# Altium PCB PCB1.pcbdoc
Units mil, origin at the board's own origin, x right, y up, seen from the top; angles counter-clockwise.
Board outline 3432.54 x 1243.82 mil, 4 copper layers (Top Layer, GND, VCC, Bottom Layer); 58 components, 43 nets, 212 pads, 108 vias.
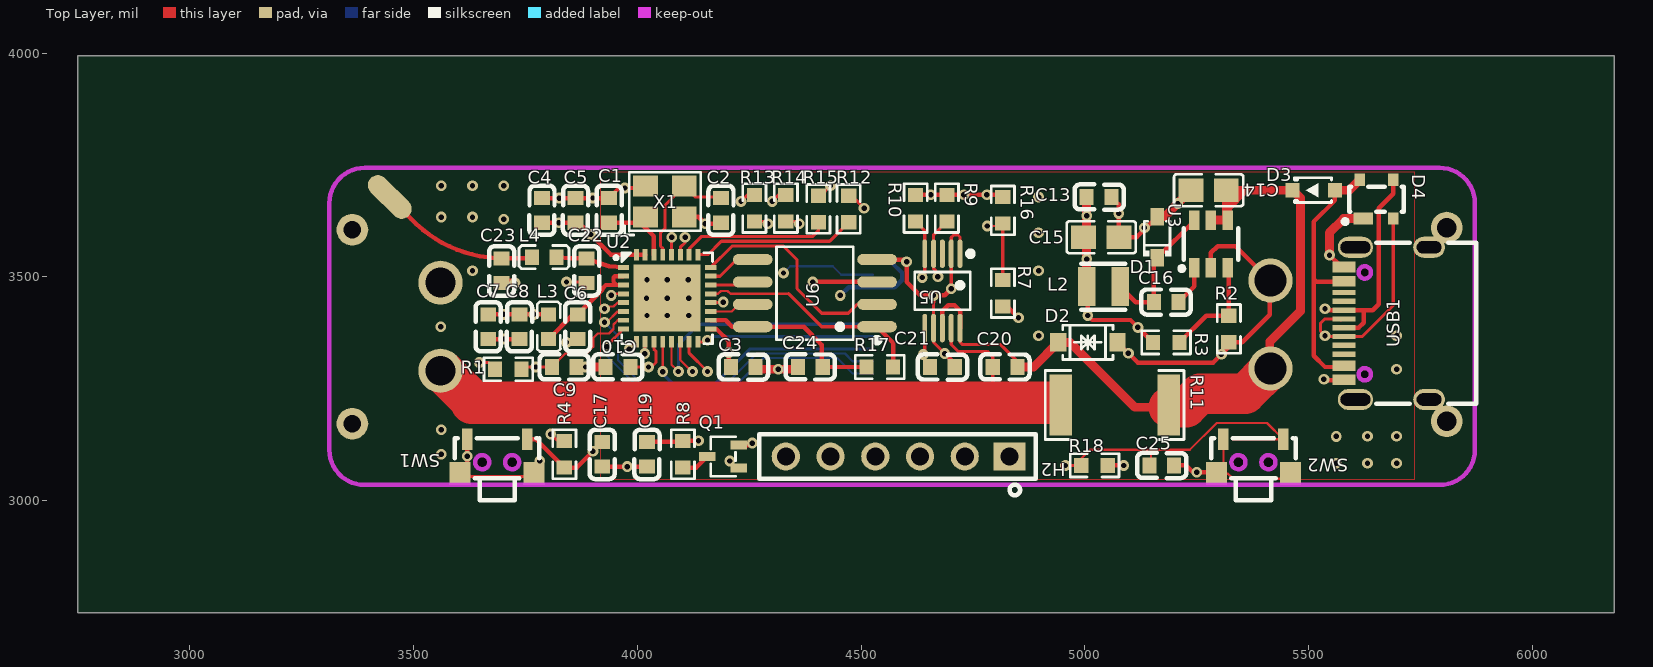
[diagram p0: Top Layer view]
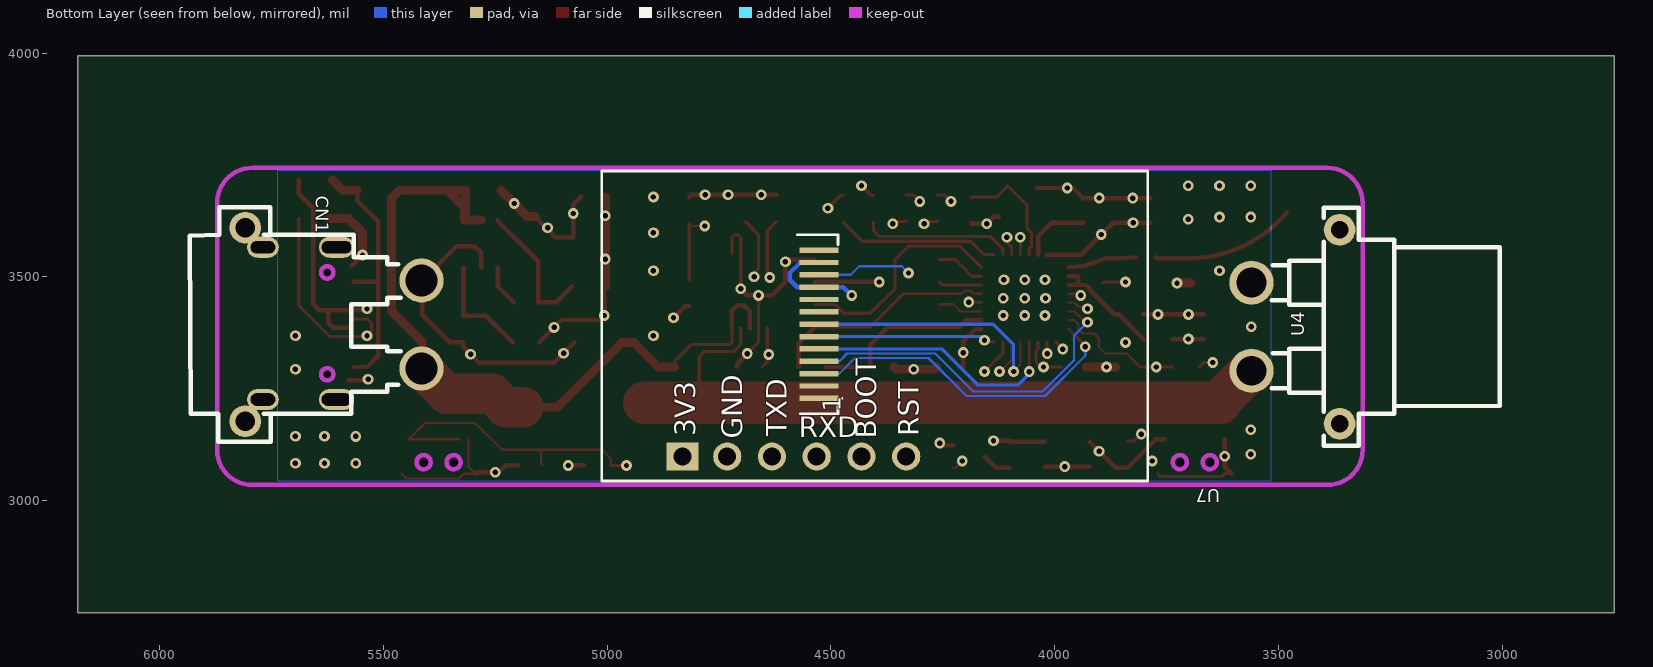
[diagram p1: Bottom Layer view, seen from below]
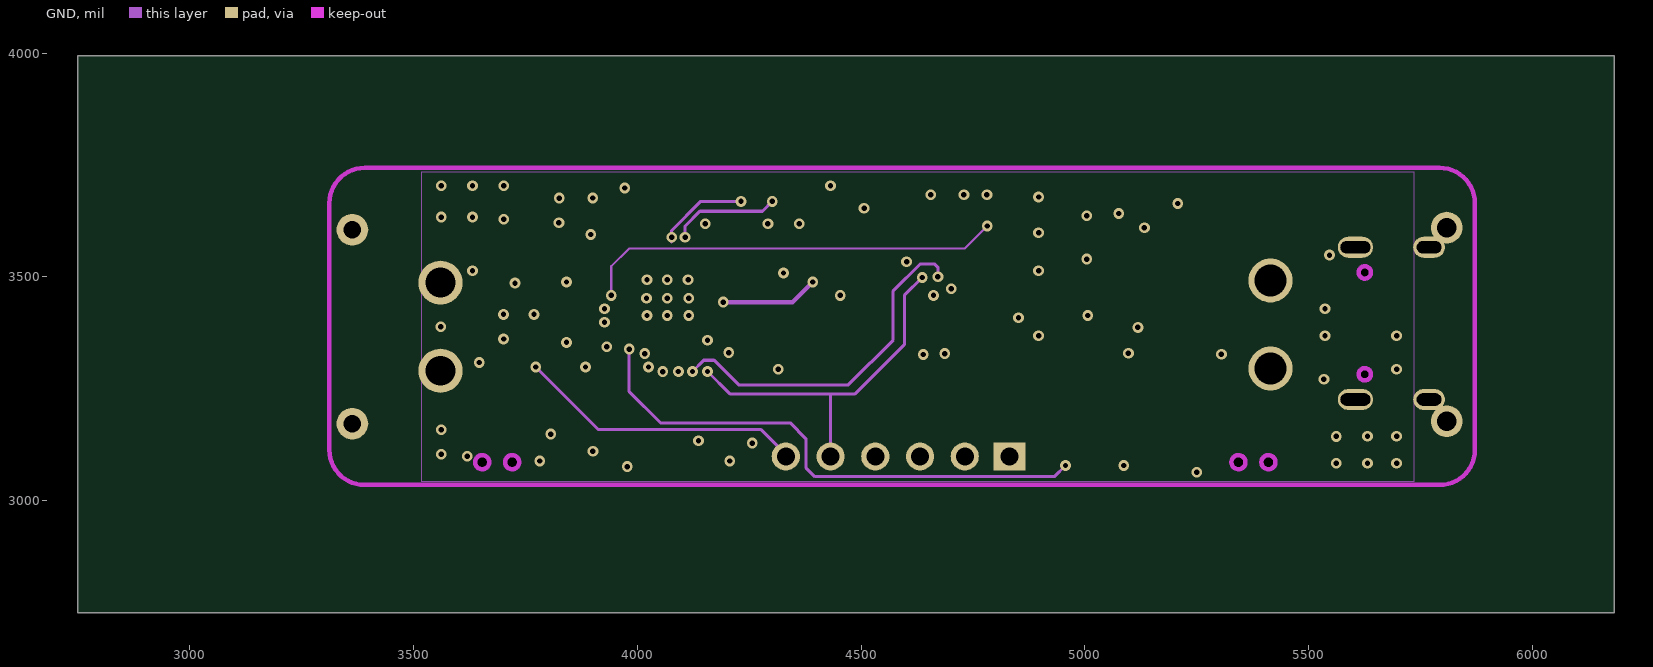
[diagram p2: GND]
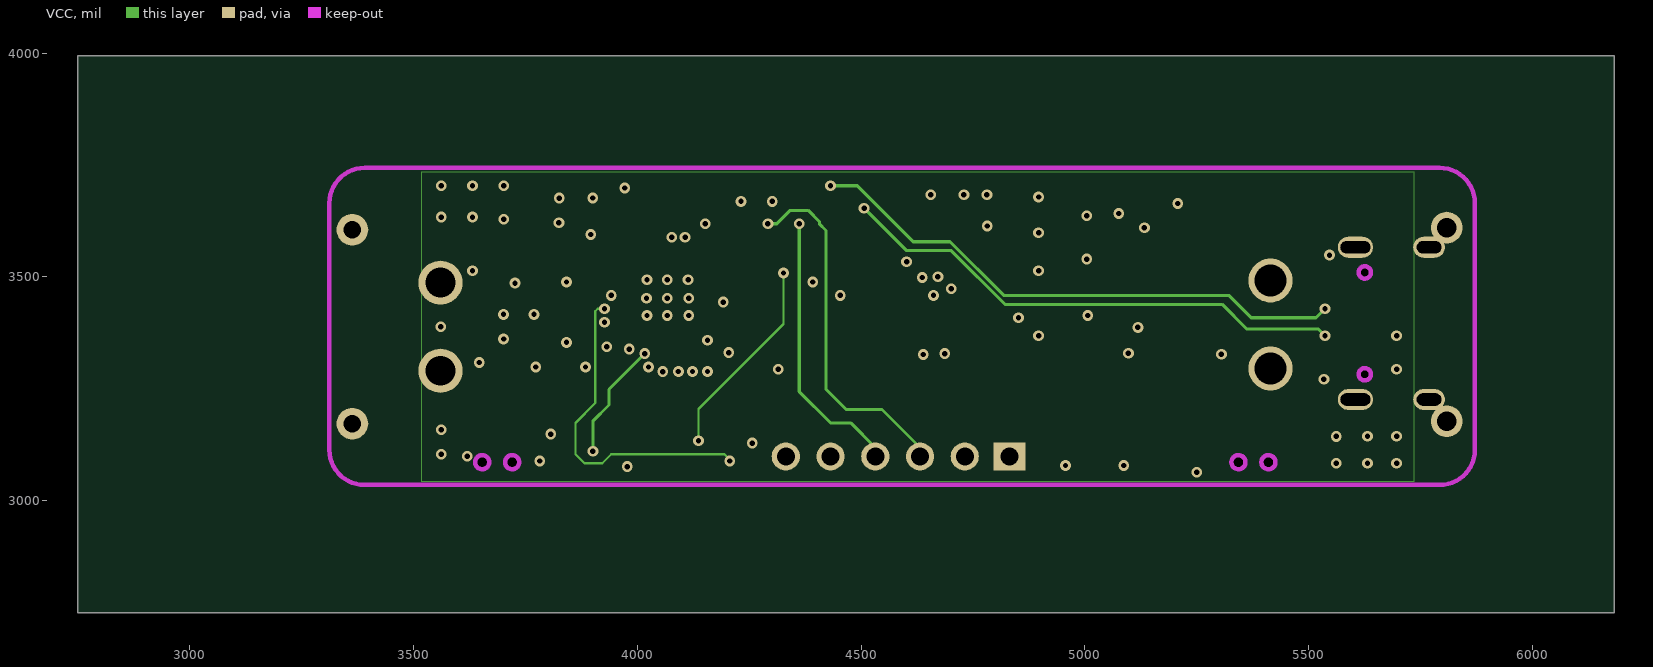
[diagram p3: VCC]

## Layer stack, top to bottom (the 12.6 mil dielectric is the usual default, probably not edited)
Top Layer: signal copper (thickness not stored)
Dielectric: dielectric 12.6, FR-4, Dk 4.8
GND: signal copper (thickness not stored)
Dielectric: dielectric 12.6, FR-4, Dk 4.8
VCC: signal copper (thickness not stored)
Dielectric: dielectric 12.6, FR-4, Dk 4.8
Bottom Layer: signal copper (thickness not stored)

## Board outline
6182.54,2750 2750,2750 2750,3993.82 6182.54,3993.82

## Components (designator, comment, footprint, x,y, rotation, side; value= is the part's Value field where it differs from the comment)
C1 "CC0603JRNPO9BN220" C0603 3936.69,3648.82 r270 top
C2 "CC0603JRNPO9BN220" C0603 4186.69,3648.82 r270 top
C3 "0603B104K500NT" C0603 4236.69,3298.82 r180 top
C4 "CL10A105KB8NNNC" C0603 3786.69,3648.82 r270 top
C5 "CL10A106KP8NNNC" C0603 3861.69,3648.82 r270 top
C6 "CL10A105KB8NNNC" C0603 3866.69,3388.82 r90 top
C7 "CL10A106KP8NNNC" C0603 3666.69,3388.82 r90 top
C8 "0603B104K500NT" C0603 3736.69,3388.82 r90 top
C9 "0603B104K500NT" C0603 3836.69,3298.82 r0 top
C10 "0603B104K500NT" C0603 3956.69,3298.82 r0 top
C13 "0603B104K500NT" C0603 5031.69,3678.82 r180 top
C14 "CL21A475KAQNNNE" C0805 5276.69,3693.82 r0 top
C15 "CL21A226MAQNNNE" C0805 5036.69,3588.82 r180 top
C16 "0603B104K500NT" C0603 5181.69,3443.82 r0 top
C17 "0603B104K500NT" C0603 3921.69,3103.82 r90 top
C19 "CL10A106KP8NNNC" C0603 4021.69,3103.82 r90 top
C20 "0603B104K500NT" C0603 4821.69,3298.82 r0 top
C21 "0603B104K500NT" C0603 4681.69,3298.82 r180 top
C22 "CAP_0603" C0603 3886.69,3513.82 r90 top
C23 "CAP_0603" C0603 3696.69,3513.82 r90 top
C24 "CL10A105KB8NNNC" C0603 4386.69,3298.82 r0 top
C25 "0603B104K500NT" C0603 5171.69,3078.82 r180 top
CN1 "XT30PW-M" CONN-TH_XT30PW-M 5611.69,3393.82 r270 bottom
D1 "1N5819WS_C191023" SOD-323_L1.8-W1.3-LS2.5-RD 5161.69,3588.82 r90 top
D2 "SMF26CA_C435495" SOD-123_L2.8-W1.8-LS3.7-BI 5006.69,3353.82 r0 top
D3 "S7116-300A" SOD-323_L1.7-W1.3-LS2.5-RD 5511.69,3693.82 r0 top
D4 "BST143A053U" SOT-143_L2.9-W1.3-P1.92-LS2.3-BR 5651.69,3673.82 r270 top
H2 "HDR-F_2.54_1x6P" HDR-TH_6P-P2.54-V-F 4581.69,3098.82 r180 top
L2 "FHD252012S-100MT" IND-SMD_L2.5-W2.0_FHD252012S-6R8MT 5041.69,3478.82 r180 top
L3 "VHF160808H2N0ST" L0603 3801.69,3388.82 r270 top
L4 "L_0603" L0603 3791.69,3543.82 r0 top
Q1 "DTC114EUA_C55054" SOT-323-3_L2.0-W1.3-P1.30-LS2.1-BR 4191.69,3098.82 r0 top
R1 "0603WAF1002T5E" R0603 3711.69,3293.82 r0 top
R2 "RT0603BRD071K02L" R0603 5321.69,3383.82 r90 top
R3 "RT0603BRD073K4L" R0603 5181.69,3353.82 r0 top
R4 "0603WAF1002T5E" R0603 3836.69,3103.82 r90 top
R7 "0603WAF1002T5E" R0603 4816.69,3463.82 r90 top
R8 "0603WAF100JT5E" R0603 4101.69,3103.82 r90 top
R9 "0603WAF4701T5E" R0603 4691.69,3653.82 r270 top
R10 "0603WAF4701T5E" R0603 4621.69,3653.82 r270 top
R11 "PA2512FKE7T0R01E" R2512 5066.69,3213.82 r180 top
R12 "0603WAF390JT5E" R0603 4472.2,3652.04 r270 top
R13 "0603WAF3300T5E" R0603 4261.69,3653.82 r90 top
R14 "0603WAF3300T5E" R0603 4331.69,3653.82 r90 top
R15 "0603WAF390JT5E" R0603 4404.51,3652.04 r270 top
R16 "SDNT1608X103F3450FTF" R0603 4816.69,3648.82 r90 top
R17 "0603WAF1002T5E" R0603 4541.69,3298.82 r180 top
R18 "0603WAF1002T5E" R0603 5021.69,3078.82 r0 top
SW1 "TS-1010-C-A" KEY-SMD_TX-1010-X-X 3686.69,3098.82 r180 top
SW2 "TS-1010-C-A" KEY-SMD_TX-1010-X-X 5376.69,3098.82 r180 top
U2 "ESP32-C3" QFN-32_L5.0-W5.0-P0.50-TL-EP3.7 4066.55,3452.51 r0 top
U3 "LM2841XBMKX/NOPB" SOT-23-6_L2.9-W1.6-P0.95-LS2.8-BR 5281.69,3573.82 r270 top
U4 "XT30PW-F" CONN-TH_XT30PW-F-1 3461.69,3388.82 r90 bottom
U5 "INA226AIDGSR" MSOP-10_L3.0-W3.0-P0.50-LS5.0-BL 4681.69,3468.82 r180 top
U6 "W25Q128JVSIQ" SOIC-8_L5.3-W5.3-P1.27-LS8.0-BL 4396.69,3463.82 r90 top
U7 "ST7789" ST7789 4526.69,3228.82 r0 bottom
USB1 "HC-TYPE-C-16P-01B" USB_TYPE-C-16P 5674.19,3391.32 r90 top
X1 "X322540MPB4SI" OSC-SMD_4P-L3.2-W2.5-BL 4061.69,3668.82 r0 top

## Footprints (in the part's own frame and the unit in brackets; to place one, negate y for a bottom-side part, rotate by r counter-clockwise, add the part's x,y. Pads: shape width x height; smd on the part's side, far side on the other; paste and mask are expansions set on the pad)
C0603 [mm]
  rect 0.8x0.9 smd: 1(-0.7,0) 2(0.7,0)
  silkscreen extent -1.41,-0.71 1.39,0.72
C0805 [mm]
  rect 1.41x1.35 smd: 1(-1,0) 2(1,0)
  silkscreen extent -1.96,-0.9 1.96,0.9
CONN-TH_XT30PW-F-1 [mm]
  round 2.5 hole 1.7 copper offset 0,0: 1(-2.5,2.5) 2(2.5,2.5)
  round 1.8 hole 1 copper offset 0,0: 3(5.5,-2.5) 4(-5.5,-2.5)
  silkscreen extent -6.75,-11.6 6.75,1.35
CONN-TH_XT30PW-M [mm]
  round 2.5 hole 1.8: 1(-2.5,5) 2(2.5,5)
  round 1.8 hole 1.1: 3(5.5,-5) 4(-5.5,-5)
  silkscreen extent -6.65,-8.15 6.65,3.81
HDR-TH_6P-P2.54-V-F [mm]
  rect 1.8x1.6 hole 1.02: 1(-6.35,0)
  round 1.6 hole 1.02: 2(-3.81,0) 3(-1.27,0) 4(1.27,0) 5(3.81,0) 6(6.35,0)
  silkscreen extent -7.85,-1.25 7.85,2.2
IND-SMD_L2.5-W2.0_FHD252012S-6R8MT [mm]
  rect 1x2.2 smd: 1(-0.951,0) 2(0.95,0)
  silkscreen extent -1.24,-1.3 1.26,1.32
KEY-SMD_TX-1010-X-X [mm]
  rect 0.6x1.2 smd: 1(-1.7,-0.975) 2(1.7,-0.975)
  rect 1.2x1.3 smd: 3(-2.1,0.975) 4(2.1,0.975)
  Multi-Layer board cut-out: -1.25,0.325 -1.21,0.151 -1.099,0.012 -0.939,-0.065 -0.761,-0.065 -0.6,0.012 -0.489,0.152 -0.45,0.325 -0.45,0.325 -0.489,0.499 -0.6,0.638 -0.761,0.715 -0.939,0.715 -1.099,0.638 -1.21,0.499 -1.25,0.325
  Multi-Layer board cut-out: 0.45,0.325 0.49,0.151 0.601,0.012 0.761,-0.065 0.939,-0.065 1.1,0.012 1.211,0.152 1.25,0.325 1.25,0.325 1.211,0.499 1.1,0.638 0.939,0.715 0.761,0.715 0.601,0.638 0.49,0.499 0.45,0.325
  silkscreen extent -2.4,-1.03 2.4,2.48
L0603 [mm]
  rect 0.8x0.864 smd: 1(-0.7,0) 2(0.7,0)
  silkscreen extent -1.42,-0.65 1.41,0.67
MSOP-10_L3.0-W3.0-P0.50-LS5.0-BL [mm]
  oval 0.28x1.62 smd: 1(-1,-2.11) 2(-0.5,-2.11) 3(0,-2.11) 4(0.5,-2.11) 5(1,-2.11) 6(1,2.11) 7(0.5,2.11) 8(0,2.11) 9(-0.5,2.11) 10(-1,2.11)
  silkscreen extent -1.74,-2.26 1.58,1.07
OSC-SMD_4P-L3.2-W2.5-BL [mm]
  rect 1.4x1.2 smd: 1(-1.1,-0.875) 2(1.1,-0.875) 3(1.1,0.875) 4(-1.1,0.875)
  silkscreen extent -2.29,-1.9 2.03,1.65
QFN-32_L5.0-W5.0-P0.50-TL-EP3.7 [mm]
  rect 0.65x0.28 smd: 1(-2.478,1.75) 2(-2.478,1.25) 3(-2.478,0.75) 4(-2.478,0.25) 5(-2.478,-0.25) 6(-2.478,-0.75) 7(-2.478,-1.25) 8(-2.478,-1.75) 17(2.478,-1.75) 18(2.478,-1.25) 19(2.478,-0.75) 20(2.478,-0.25) 21(2.478,0.25) 22(2.478,0.75) 23(2.478,1.25) 24(2.478,1.75)
  rect 0.28x0.65 smd: 9(-1.75,-2.478) 10(-1.25,-2.478) 11(-0.75,-2.478) 12(-0.25,-2.478) 13(0.25,-2.478) 14(0.75,-2.478) 15(1.25,-2.478) 16(1.75,-2.478) 25(1.75,2.478) 26(1.25,2.478) 27(0.75,2.478) 28(0.25,2.478) 29(-0.25,2.478) 30(-0.75,2.478) 31(-1.25,2.478) 32(-1.75,2.478)
  rect 3.8x3.8 smd: 33(0,0)
  silkscreen extent -3,-2.58 2.58,2.58
R0603 [mil]
  rect 31.75x34.02 smd: 1(-29.66,0) 2(29.66,0)
  silkscreen extent -55,-26 55,26
R2512 [mil]
  rect 50.49x136.06 smd: 1(-120.72,0) 2(120.72,0)
  silkscreen extent -155,-77 155,77
SOD-123_L2.8-W1.8-LS3.7-BI [mm]
  rect 0.93x1.06 smd: 1(1.685,0) 2(-1.685,0)
  silkscreen extent -1.43,-0.98 1.43,0.98
SOD-323_L1.7-W1.3-LS2.5-RD [mm]
  rect 0.8x0.8 smd: 1(-1.2,0) 2(1.2,0)
  silkscreen extent -1.1,-0.7 1,0.7
SOD-323_L1.8-W1.3-LS2.5-RD [mm]
  rect 1x0.75 smd: 1(-1.173,0) 2(1.173,0)
  silkscreen extent -1.08,-0.8 0.9,0.8
SOIC-8_L5.3-W5.3-P1.27-LS8.0-BL [mm]
  oval 0.63x2.25 smd: 1(-1.905,-3.53) 2(-0.635,-3.53) 3(0.635,-3.53) 4(1.905,-3.53) 5(1.905,3.53) 6(0.635,3.53) 7(-0.635,3.53) 8(-1.905,3.53)
  silkscreen extent -2.82,-3.68 2.64,2.18
SOT-23-6_L2.9-W1.6-P0.95-LS2.8-BR [mm]
  rect 1.1x0.6 smd: 1(1.35,-0.95) 2(1.35,0) 3(1.35,0.95) 4(-1.35,0.95) 5(-1.35,0) 6(-1.35,-0.95)
  silkscreen extent -0.9,-1.78 1.52,1.55
SOT-143_L2.9-W1.3-P1.92-LS2.3-BR [mm]
  rect 0.7x1.1 smd: 1(1.1,-0.75)
  rect 0.7x0.6 smd: 2(1.1,0.95) 3(-1.1,0.95) 4(-1.1,-0.95)
  silkscreen extent -0.7,-1.9 1.4,1.55
SOT-323-3_L2.0-W1.3-P1.30-LS2.1-BR [mm]
  rect 0.936x0.5 smd: 1(0.898,-0.65) 2(0.898,0.65) 3(-0.898,0)
  silkscreen extent -0.7,-1.13 0.7,1.13
ST7789 [mil]
  rect 86.34x12.11 smd: 1(0,0) 2(0,-27.6) 3(0,-55.2) 4(0,-82.8) 5(0,-110.4) 6(0,-138) 7(0,-165.6) 8(0,-193.2) 9(0,-220.8) 10(0,-248.4) 11(0,-276) 12(0,-303.6) 13(0,-331.2)
  silkscreen extent -735,-508 485,185
USB_TYPE-C-16P [mm]
  oval 1.2x2 hole 0.7 slot 1.7 at 90 deg: 1(-4.193,1.765) 2(4.447,1.765)
  oval 1.2x1.8 hole 0.7 slot 1.4 at 90 deg: 3(-4.193,-2.415) 4(4.447,-2.415)
  rect 0.3x1.3 smd: A1(-3.223,2.415) A4(-2.423,2.415) A5(-1.123,2.415) A6(-0.123,2.415) A7(0.377,2.415) A8(1.377,2.415) A9(2.677,2.415) A12(3.477,2.415) B1(3.177,2.415) B4(2.377,2.415) B5(1.877,2.415) B6(0.877,2.415) B7(-0.623,2.415) B8(-1.623,2.415) B9(-2.123,2.415) B12(-2.923,2.415)
  Multi-Layer board cut-out: -2.763,0.885 -2.611,0.92 -2.489,1.017 -2.422,1.157 -2.422,1.313 -2.489,1.453 -2.611,1.55 -2.763,1.585 -2.763,1.585 -2.938,1.538 -3.066,1.41 -3.113,1.235 -3.066,1.06 -2.938,0.932 -2.763,0.885
  Multi-Layer board cut-out: 3.017,0.885 3.169,0.92 3.291,1.017 3.358,1.157 3.358,1.313 3.291,1.453 3.169,1.55 3.017,1.585 3.017,1.585 2.842,1.538 2.714,1.41 2.667,1.235 2.714,1.06 2.842,0.932 3.017,0.885
  silkscreen extent -4.45,-5.08 4.7,0.57

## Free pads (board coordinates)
  oval 120x45 smd rot 135: 1(3446.69,3678.82)

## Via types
v1: diameter 24.02, hole 12.01, Top Layer to Bottom Layer, 108 vias

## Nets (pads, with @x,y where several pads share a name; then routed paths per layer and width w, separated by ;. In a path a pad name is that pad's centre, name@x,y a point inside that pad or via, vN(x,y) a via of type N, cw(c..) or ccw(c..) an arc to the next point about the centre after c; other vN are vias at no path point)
3V3: C3.2 C4.2 C5.2 C7.2 C8.2 C10.2 C13.2 C15.2 C21.2 H2.1 L2.2 L3.1 R1.1 R3.1 R4.2 R9.1 R10.1 R16.2 R18.2 U2.11 U2.17 U2.31 U2.32 U5.6 U7.10 U7.12 | length 1687.4
  Top Layer w7: v1(3646.69,3308.82) 3667.03,3308.82 R1.1@3677.03,3298.82 ; v1(3806.69,3148.82) 3822.03,3133.48 R4.2 ; C10.2 4031.69,3298.82 4041.69,3308.82 4041.69,3334.15 4037.02,3338.82 U2.11 ; U5.6 4642.32,3310.63 C21.2
  Top Layer w10: C7.2 v1(3700.94,3416.38) C8.2 v1(3769.05,3416.38) L3.1 ; C4.2 v1(3824.67,3621.26) C5.2 3869.25,3621.26 v1(3895.64,3594.87) 3940.46,3550.05 U2.32 U2.31 ; U2.17 4176.9,3383.61 4204.13,3356.38 v1(4204.13,3331.05) C3.2@4204.13,3298.82 ; R10.1 v1(4655.4,3683.48) R9.1 v1(4729.78,3683.48) v1(4781.1,3683.48) 4811.69,3683.48 R16.2 ; L2.2 5006.69,3476.41 v1(5006.69,3413.82) 5016.69,3403.82 5102.03,3403.82 v1(5118.54,3387.31) R3.1 ; R18.2 v1(5086.69,3078.82)
  Top Layer w20: C13.2 v1(5004.13,3636.57) v1(5004.13,3539.96) 5004.13,3478.97 L2.2
  Bottom Layer w10: v1(4453.61,3458.75) 4472.08,3477.22 U7.10 4575.09,3477.22 4591.69,3493.82 4591.69,3508.82 4568.09,3532.42 U7.12
  other v1: 4025.03,3298.81 4639.16,3326.77
5V: D3.2 D4.4 USB1.A4 USB1.A9 USB1.B4 USB1.B9 | length 575.7
  Top Layer w10: D3.2 5558.93,3671.06 5511.69,3623.82 5511.69,3495.4 ; USB1.A4@5565.19,3298.82 5536.69,3298.82 5511.69,3323.82 5511.69,3495.4 ; USB1.B4@5566.22,3488.82 5518.28,3488.82 5511.69,3495.4
  Top Layer w20: D3.2 5590.98,3693.82 D4.4
$1N2271: R12.2 U2.25 | length 366.7
  Top Layer w7: U2.25 4157.92,3550.05 4187.69,3579.82 4429.64,3579.82 R12.2
$1N2275: R15.2 U2.26 | length 337.6
  Top Layer w7: U2.26 4115.76,3562.89 4143.69,3590.82 4392.33,3590.82 4404.51,3603.01 R15.2
$1N2279: R14.2 U2.27 | length 329.1
  Top Layer w7: U2.27 4096.08,3566.35 4106.69,3576.96 v1(4106.69,3588.82) v1@4101.69,3593.82 ; v1(4301.69,3668.82) 4316.35,3683.48 R14.2
  GND w7: v1(4106.69,3588.82) 4106.69,3613.82 4139.69,3646.82 4279.69,3646.82 v1(4301.69,3668.82)
$1N2283: R13.2 U2.28 | length 281.9
  Top Layer w7: U2.28 4076.69,3550.35 v1(4076.69,3588.82) ; v1(4231.69,3668.82) 4246.35,3683.48 R13.2
  GND w7: v1@4076.69,3578.82 v1(4076.69,3588.82) 4076.69,3603.82 4141.69,3668.82 v1(4231.69,3668.82)
$1N2291: C2.1 U2.29 X1.3 | length 270.2
  Top Layer w7: U2.29 4056.71,3563.8 4051.69,3568.82 4051.69,3598.82 4061.69,3608.82 4061.69,3659.96 X1.3 4129.45,3678.82 4184.25,3678.82 C2.1
$1N2297: C1.2 U2.30 X1.1 | length 153.7
  Top Layer w10: C1.2 4006.49,3621.26 4037.02,3590.73 U2.30
$1N3406: C16.2 U3.1 | length 91.4
  Top Layer w10: C16.2 5244.29,3478.86 U3.1
$1N3430: R2.2 R3.2 U3.3 | length 243.3
  Top Layer w10: R3.2 5271.01,3413.48 R2.2 5321.69,3518.07 U3.3
$1N3499: C16.1 D1.1 L2.1 U3.6 | length 310
  Top Layer w10: L2.1 5114.12,3443.82 C16.1 5154.13,3535.09 D1.1 5244.29,3625.25 U3.6
$1N4049: Q1.3 R8.1 | length 64.9
  Top Layer w10: R8.1 4131.68,3074.16 Q1.3
$1N6152: C22.2 L4.2 U2.1 | length 153
  Top Layer w10: L4.2 3851.69,3541.38 C22.2 3906.69,3533.82 3936.69,3523.82 U2.1
$1N9079: C6.2 L3.2 U2.2 U2.3 | length 261.9
  Top Layer w10: L3.2 3856.81,3416.38 C6.2 3921.69,3471.38 3921.69,3473.82 3929.91,3482.04 3953.47,3482.04 ; U2.3 3953.47,3482.04 ; U2.2 3949.59,3501.72 3946.69,3498.82 3946.69,3488.82 3953.47,3482.04
ANT: C23.2 L4.1 pad.1 | length 324
  Top Layer w10: pad.1@3481.69,3643.82 ccw(c3701.69,3828.83) 3701.69,3541.38 3771.7,3541.38 L4.1@3774.14,3543.82
GND: C1.1 C2.2 C3.1 C4.1 C5.1 C6.1 C7.1 C8.1 C9.2 C10.1 C13.1 C14.1 C15.1 C17.1 C19.1 C21.1 C22.1 C23.1 C24.1 C25.1 CN1.1 D1.2 D2.1 D4.1 H2.2 Q1.2 R2.1 R7.1 SW1.2 SW1.3 SW1.4 SW2.2 SW2.3 SW2.4 U2.33 U3.2 U4.2 U5.1 U5.2 U5.7 U6.4 U7.8 U7.13 USB1.A1 USB1.A12 USB1.B1 USB1.B12 X1.2 X1.4 | length 3236
  Top Layer w5: SW2.2 5309.76,3076.18 SW2.4 5320.08,3060.43 5331.04,3049.47 5448.41,3049.47 SW2.3
  Top Layer w7: SW1.4 3620.08,3060.43 3626.69,3053.82 3762.76,3053.82 SW1.3 ; v1(3841.69,3488.82) 3889.13,3488.82 C22.1@3891.69,3486.26 ; 4661.69,3443.82 4662,3443.51 U5.7 4662,3353.51 v1(4686.69,3328.82) ; v1(4701.69,3473.82) 4701.37,3474.14 U5.2 4701.37,3588.5 4706.69,3593.82 4716.69,3593.82 4721.06,3589.45 U5.1
  Top Layer w10: SW1.4 3619.76,3076.18 v1(3619.76,3099.29) SW1.2 ; C7.1 v1(3701.12,3361.26) C8.1 ; C4.1 C5.1 v1(3900.42,3676.38) C1.1 3959.13,3698.82 v1(3971.69,3698.82) X1.4@4038.93,3698.82 ; C17.1 v1(3977.17,3076.26) C19.1 ; X1.2@4124.4,3634.37 4136.14,3634.37 v1(4151.69,3618.82) 4184.25,3618.82 C2.2 ; Q1.2 4252.28,3124.41 v1(4256.69,3128.82) ; U6.4 4596.69,3538.82 v1(4601.69,3533.82) 4601.69,3488.82 4631.69,3458.82 v1(4661.69,3458.82) ; 4661.69,3443.82 v1(4661.69,3458.82) ; v1(4686.69,3328.82) 4709.25,3306.26 C21.1 ; v1(4701.69,3473.82) 4686.69,3458.82 v1(4661.69,3458.82) ; R7.1 4826.35,3434.16 v1(4851.69,3408.82) ; C13.1 5076.06,3662.01 v1(5076.06,3641.96) C15.1 5115.53,3588.82 D1.2 ; D2.1 v1(5097.41,3329.44) 5118.03,3308.82 5286.69,3308.82 v1(5305.21,3327.34) 5321.69,3343.82 R2.1 5352.03,3354.16 5413.27,3415.39 5413.27,3492.24 5336.69,3568.82 5296.69,3568.82 5281.69,3553.82 U3.2 ; C25.1 5226.69,3078.82 5241.69,3063.82 5290.63,3063.82 SW2.4 ; v1(5534.19,3271.32) 5536.08,3269.43 USB1.A1@5579.11,3269.43 ; v1(5546.69,3548.82) USB1.A12@5570.71,3524.8
  Top Layer w20: C23.1 v1(3726.69,3486.26) ; C9.2 v1(3884.21,3298.82) C10.1 ; C3.1 4269.25,3293.82 v1(4314.69,3293.82) 4354.13,3293.82 C24.1 ; D1.2 5178.49,3634.98 v1(5207.72,3664.22) C14.1 ; v1(5546.69,3548.82) 5546.69,3598.82 5578.39,3630.51 D4.1
  Bottom Layer w20: v1@3726.69,3483.82 v1(3726.69,3486.26)
  other v1: 5250.06,3063.82 5561.69,3083.82 5631.69,3083.82 5696.69,3083.82 3781.69,3088.82 3561.69,3103.82 5561.69,3143.71 5631.69,3143.82 5696.69,3143.82 3561.69,3158.82 5696.69,3293.82 3841.69,3353.82 4896.69,3368.82 5696.69,3368.82 3560.54,3388.82 4021.69,3413.82 4066.55,3413.82 4115.05,3413.82 4020.54,3452.51 4066.55,3452.51 4114.71,3452.51 4021.69,3493.82 4066.55,3493.82 4113.37,3493.82 3631.69,3513.82 4896.69,3513.82 4896.69,3598.82 5133.1,3610.26 3701.69,3628.82 3561.69,3633.82 3631.69,3633.82 3825.67,3676.21 4896.69,3678.82 3561.69,3703.82 3631.69,3703.82 3701.69,3703.82
INA_SCL: H2.5 R10.2 U2.15 U5.5 | length 1032.2
  Top Layer w7: U2.15 4115.76,3329.75 v1(4156.69,3288.82) ; R10.2 4642.32,3603.53 U5.5 4642.32,3504.45 v1(4636.69,3498.82)
  GND w7: v1(4156.69,3288.82) 4206.69,3238.82 4431.69,3238.82 ; H2.5 4431.69,3238.82 ; v1(4636.69,3498.82) 4596.69,3458.82 4596.69,3348.82 4486.69,3238.82 4431.69,3238.82
INA_SDA: R9.2 U2.14 U5.4 | length 983.4
  Top Layer w5: U2.14 4096.08,3314.43 v1@4116.69,3293.82
  Top Layer w7: v1(4671.69,3500.61) 4671.69,3508.82 4662,3518.51 U5.4 4662,3594.47 R9.2
  GND w7: v1(4123.14,3288.82) 4148.14,3313.82 4171.69,3313.82 4226.69,3258.82 4471.69,3258.82 4571.69,3358.82 4571.69,3468.82 4631.69,3528.82 4664.69,3528.82 4671.69,3521.82 v1@4671.69,3508.82
IO0_NTC: R7.2 R16.1 U2.4 | length 1134
  Top Layer w5: v1(3941.69,3458.82) 3945.22,3462.35 U2.4 ; v1(4781.69,3613.82) 4811.35,3613.82 R16.1
  Top Layer w7: R7.2 R16.1
  GND w5: v1(3941.69,3458.82) 3941.69,3523.82 3981.69,3563.82 4731.69,3563.82 v1(4781.69,3613.82)
IO1_BL: Q1.1 U2.5 | length 805.1
  Top Layer w5: v1(3926.69,3428.82) 3931.69,3433.82 3946.69,3433.82 3955.54,3442.67 U2.5 ; v1(4206.69,3088.82) 4222.28,3073.23 Q1.1
  VCC w5: v1(3926.69,3428.82) 3911.69,3428.82 3906.18,3423.31 3906.18,3218.31 3861.69,3173.82 3861.69,3103.82 3881.69,3083.82 3921.69,3083.82 3941.69,3103.82 4194.64,3103.82 4206.69,3091.77 v1(4206.69,3088.82)
IO4_K2: C25.2 R18.1 SW2.1 U2.9 | length 1920.5
  Top Layer w5: R18.1 4992.03,3094.16 5011.69,3113.82 5148,3113.82 ; C25.2 5148,3082.69 5148,3113.82 ; 5330.06,3137.2 SW2.1 5407.01,3173.82 5294.62,3173.82 5234.62,3113.82 5148,3113.82
  Top Layer w7: v1(3981.69,3338.82) 3981.69,3339.01 U2.9 ; v1(4956.69,3078.82) R18.1
  GND w7: v1(3981.69,3338.82) 3981.69,3243.82 4051.69,3173.82 4341.69,3173.82 4376.69,3138.82 4376.69,3073.82 4396.69,3053.82 4931.69,3053.82 v1(4956.69,3078.82)
IO5_K1: C17.2 R4.1 SW1.1 U2.10 | length 507.8
  Top Layer w7: v1@4011.69,3333.82 4017.34,3339.47 U2.10
  Top Layer w10: SW1.1 3773.65,3137.2 R4.1 3864.47,3074.16 v1(3900.71,3110.4) C17.2
  VCC w7: v1(3900.71,3110.4) 3900.71,3177.84 3936.69,3213.82 3936.69,3248.82 v1(4016.69,3328.82)
LEDK: C19.2 R8.2 U7.11 | length 783.8
  Top Layer w10: C19.2 4099.59,3131.38 R8.2 4102.03,3133.82 v1(4136.69,3133.82)
  VCC w5: v1(4136.69,3133.82) 4136.69,3204.82 4326.69,3394.82 v1(4326.69,3508.82)
  Bottom Layer w5: v1(4326.69,3508.82) 4341.69,3523.82 4436.69,3523.82 4455.69,3504.82 U7.11
MOSI: U2.8 U7.3 | length 757.2
  Top Layer w7: v1(3931.69,3343.82) 3931.69,3346.29 U2.8
  Bottom Layer w5: v1(3931.69,3343.82) 3931.69,3323.82 4021.69,3233.82 4196.69,3233.82 4281.69,3318.82 4446.69,3318.82 4481.49,3284.02 U7.3
RESET: C9.1 H2.6 R1.2 U2.7 | length 937.9
  Top Layer w5: C9.1 3839.13,3328.82 3886.69,3328.82 3901.69,3343.82 3901.69,3363.82 3911.69,3373.82 3936.69,3373.82 3946.69,3383.82 3946.69,3393.82 3956.17,3403.3 U2.7
  Top Layer w7: R1.2@3736.35,3298.82 v1(3773.09,3298.82) C9.1
  GND w7: v1(3773.09,3298.82) 3913.09,3158.82 4276.69,3158.82 4331.69,3103.82 H2.6
RXD: H2.4 R14.1 | length 649
  Top Layer w7: R14.1 4356.35,3624.16 v1(4361.69,3618.82)
  VCC w7: v1(4361.69,3618.82) 4361.69,3243.82 4431.69,3173.82 4476.69,3173.82 4531.69,3118.82 H2.4
SCLK: U2.6 U7.4 | length 791.1
  Top Layer w5: v1(3926.69,3398.82) 3931.69,3398.82 3955.85,3422.98 U2.6
  Bottom Layer w5: v1(3926.69,3398.82) 3956.69,3368.82 3956.69,3313.82 4026.69,3243.82 4181.69,3243.82 4266.69,3328.82 4463.82,3328.82 4481.02,3311.62 U7.4
SPICLK: U2.22 U6.6 | length 96.4
  Top Layer w7: U2.22 4250.93,3482.04 U6.6
SPICS: R17.1 U2.21 U6.1 | length 512.2
  Top Layer w5: U2.21 4180.22,3462.35 4186.69,3468.82 4201.69,3468.82 4208.16,3462.35 4338.16,3462.35
  Top Layer w7: 4338.16,3462.35 4411.69,3388.82 U6.1
  Top Layer w10: U6.1 4571.35,3353.14 R17.1
SPID: U2.23 U6.5 | length 109
  Top Layer w7: U2.23 4184.59,3501.72 4221.69,3538.82 U6.5
SPIHD: U2.19 U6.7 | length 100.2
  Top Layer w5: U2.19 4210.85,3422.98 4226.69,3438.82 U6.7
SPIQ: U2.24 U6.2 | length 499.7
  Top Layer w7: U2.24 4211.5,3568.82 4326.69,3568.82 4356.69,3538.82 4356.69,3473.82 4411.69,3418.82 4471.69,3418.82 4491.69,3438.82 U6.2
SPIWP: U2.20 U6.3 | length 390.7
  Top Layer w7: U2.20 4190.54,3442.67 v1(4191.69,3443.82)
  Top Layer w10: v1(4391.69,3488.82) U6.3
  GND w10: v1(4191.69,3443.82) 4346.69,3443.82 v1(4391.69,3488.82)
TFFT_CS: U2.13 U7.7 | length 579.3
  Top Layer w5: U2.13 4076.39,3304.12 v1@4086.69,3293.82
  Bottom Layer w7: v1(4091.69,3288.82) 4091.69,3348.82 4137.29,3394.42 U7.7
TFT_DC: U2.12 U7.5 | length 579.5
  Top Layer w5: v1@4056.71,3293.82 U2.12
  Bottom Layer w7: v1(4056.71,3288.54) 4056.71,3283.8 4081.69,3258.82 4171.69,3258.82 4252.09,3339.22 U7.5
TFT_RST: U2.16 U7.6 | length 396.1
  Top Layer w7: U2.16 4152.84,3354.97 v1(4156.69,3358.82)
  Bottom Layer w7: v1(4156.69,3358.82) 4164.69,3366.82 U7.6
TXD: H2.3 R13.1 | length 835.1
  Top Layer w7: R13.1 4286.35,3624.16 v1(4291.69,3618.82)
  VCC w7: v1(4291.69,3618.82) 4311.69,3618.82 4341.69,3648.82 4381.69,3648.82 4406.69,3623.82 4406.69,3618.82 4421.69,3603.82 4421.69,3248.82 4466.69,3203.82 4546.69,3203.82 4631.69,3118.82 H2.3
USB_D+: D4.3 R15.1 USB1.A6 USB1.B6 | length 1766.8
  Top Layer w7: R15.1 4409.57,3681.7 v1(4431.69,3703.82)
  Top Layer w10: v1(5536.69,3428.82) 5539.66,3425.85 USB1.B6 5623.06,3425.85 ; USB1.A6 5611.69,3386.48 5623.06,3397.84 5623.06,3425.85 ; D4.3 5689.1,3686.22 5656.69,3653.82 5656.69,3438.82 5643.72,3425.85 5623.06,3425.85
  VCC w7: v1(4431.69,3703.82) 4491.69,3703.82 4616.69,3578.82 4698.69,3578.82 4818.69,3458.82 5321.69,3458.82 5371.69,3408.82 5516.69,3408.82 v1(5536.69,3428.82)
USB_D-: D4.2 R12.1 USB1.A7 USB1.B7 | length 1652.5
  Top Layer w7: R12.1 4478.81,3681.7 v1(4506.69,3653.82) ; USB1.A7@5571.77,3403.82 5569.43,3406.17 5536.04,3406.17 5526.69,3396.82 5526.69,3379.06 5539.14,3366.62 5619.49,3366.62 5689.1,3436.22 D4.2
  VCC w7: v1(4506.69,3653.82) 4601.69,3558.82 4701.69,3558.82 4821.69,3438.82 5306.69,3438.82 5361.69,3383.82 5521.69,3383.82 v1(5536.69,3368.82)
VDDSPI: C24.2 R17.2 U2.18 U6.8 | length 419
  Top Layer w10: U2.18 4197.21,3403.3 4211.69,3388.82 U6.8 4371.69,3388.82 4411.69,3348.82 4411.69,3301.38 C24.2 R17.2
VIN: C14.2 C20.2 CN1.2 D2.2 D3.1 R11.1 U3.4 U3.5 U5.8 U5.10 | length 1767
  Top Layer w7: U5.10 4721.06,3353.82 4721.69,3353.82 4726.69,3348.82 4811.69,3348.82 4849.25,3311.26 C20.2
  Top Layer w10: U5.8 4681.69,3423.82 4694.62,3436.75 4708.76,3436.75 4721.06,3424.45 U5.10
  Top Layer w20: C20.2 4885.35,3298.82 D2.2 4966.69,3353.82 5111.69,3208.82 R11.1@5187.41,3208.82 ; U3.5 U3.4 5319.09,3656.22 5356.69,3693.82 ; U3.4@5316.06,3630 C14.2 5356.69,3693.82 ; CN1.2@5413.27,3295.39 5413.27,3355.39 5481.69,3423.82 5481.69,3676.58 D3.1 5356.69,3693.82
  Top Layer w90: R11.1@5187.41,3208.82 5226.69,3208.82 5256.69,3238.82 5358.27,3238.82 CN1.2
VOUT: C20.1 R11.2 U4.1 U5.9 | length 1594.2
  Top Layer w7: U5.9 4701.37,3349.14 4716.69,3333.82 4781.69,3333.82 4794.13,3321.38 C20.1 4794.13,3248.82
  Top Layer w95: U4.1@3568.54,3285.39 3635.12,3218.82 ; 3630.12,3218.82 3635.12,3218.82 ; 4916.69,3218.82 3635.12,3218.82
"": CN1.3 CN1.4 U4.3 U4.4 U5.3 U7.1 U7.2 U7.9 USB1.1 USB1.2 USB1.3 USB1.4 USB1.A5 USB1.A8 USB1.B5 USB1.B8

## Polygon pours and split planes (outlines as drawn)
GND on GND (solid, remove dead copper): 3516.69,3043.82 5736.69,3043.82 5736.69,3733.82 3516.69,3733.82
3V3 on VCC (solid, remove dead copper): 3516.69,3043.82 5736.69,3043.82 5736.69,3733.82 3516.69,3733.82
GND on Bottom Layer (solid, remove dead copper, pour order 6): 3516.69,3043.82 5736.69,3043.82 5736.69,3738.82 3516.69,3738.82
GND on Top Layer (solid, remove dead copper, pour order 6): 3916.69,3047.54 5736.91,3047.54 5736.91,3733.47 3916.69,3733.47

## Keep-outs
Board Outline Layer:
  lines w10 net "": 3311.69,3113.9 ccw(c3390.43,3113.9) 3390.43,3035.16 5792.95,3035.16 ccw(c5792.95,3113.9) 5871.69,3113.9 5871.69,3665.08 ccw(c5792.95,3665.08) 5792.95,3743.82 3390.43,3743.82 ccw(c3390.43,3665.08) 3311.69,3665.08 3311.69,3113.9
Multi-Layer:
  circle w10: c3720.15,3086.02 r15.75
  circle w10: c3653.22,3086.02 r15.75
  circle w10: c5410.15,3086.02 r15.75
  circle w10: c5343.22,3086.02 r15.75
  circle w10: c5625.57,3282.54 r13.78
  circle w10: c5625.57,3510.1 r13.78

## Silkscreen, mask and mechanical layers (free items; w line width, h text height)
Bottom Silkscreen Layer:
  text "RST" at 4303.33,3143.87 h45.31 r270
  text "TXD" at 4598.6,3143.87 h45.31 r270
  text "3V3" at 4803.33,3143.87 h45.31 r270
  text "RXD" at 4571.74,3142.18 h45.31
  text "BOOT" at 4398.33,3138.98 h45.31 r270
  text "GND" at 4698.33,3138.87 h45.31 r270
